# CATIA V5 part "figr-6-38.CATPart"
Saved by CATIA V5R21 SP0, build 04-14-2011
Part number: Part1
Bounding box of the stored display mesh (mm): x -42.494 to 42.494, y -51.186 to 51.186, z 0 to 35
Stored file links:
  D:\CATIA V5R21 E-RESOURCES\CATIA-V5R21\catia-v5r21-prt\c06-catia-v5r21-prt\c06-catia-v5r21-figr-6-38.CATPart
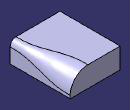
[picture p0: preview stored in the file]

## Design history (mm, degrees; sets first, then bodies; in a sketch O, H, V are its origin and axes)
Body1 (main body)
  Sketch1 on xy-plane, origin (0, 0, 0), H (1, 0, 0), V (0, 1, 0)
    line L1 (-42.4944, 51.1864) -> (42.4944, 51.1864)
    line L2 (42.4944, 51.1864) -> (42.4944, -51.1864)
    line L3 (42.4944, -51.1864) -> (-42.4944, -51.1864)
    line L4 (-42.4944, -51.1864) -> (-42.4944, 51.1864)
    axis line L5 (42.4944, -51.1864) -> (-42.4944, 51.1864)
    horizontal: L1 H, L3 H
    vertical: L2 V, L4 V
    midpoint: O L5
  Pad1: profile Sketch1, direction (0, 0, 1), length 35
  Fillet1: on edge [face of Pad1 | face of Pad1]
